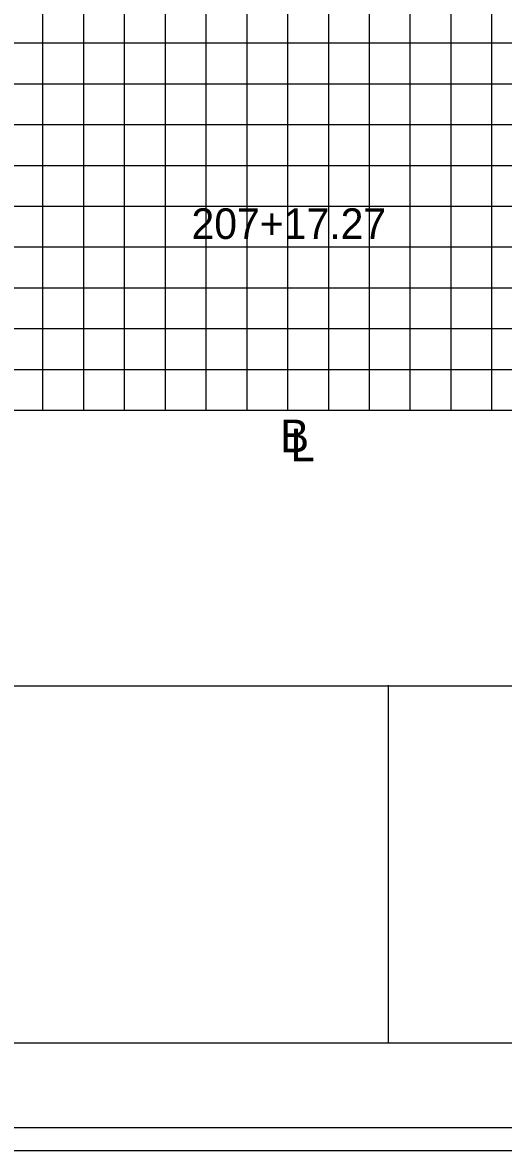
# Model space of a CAD drawing. Extents: x 967 to 1326, y 964 to 1744.
# Drawn here: x 1147 to 1170.6, y 963.7 to 1019 of the extents above; entities that cross this region are included whole.
import ezdxf

# ---------------------------------------------------------------- set-up
doc = ezdxf.new("R2010")
doc.units = 0
for name, color, linetype in [('Default', 7, 'Continuous'), ('RD_PD_PaveShd', 7, 'Continuous'), ('RD_XS_CurbBase', 7, 'Continuous'), ('RD_XS_TX_Elev_PR', 7, 'Continuous'), ('RD_XS_TX_MkPT', 7, 'Continuous'), ('RD_XS_TX_Slope', 7, 'Continuous'), ('RD_XS_TX_TOC', 7, 'Continuous')]:
    doc.layers.add(name, color=color, linetype=linetype)

msp = doc.modelspace()

# ---------------------------------------------------------------- linework, layer by layer
at = {"layer": 'RD_PD_PaveShd'}
for p, q in [((996.114, 986.486), (1323.886, 986.486)), ((1164.932, 968.983), (1164.932, 986.526)), ((1323.886, 968.983), (996.114, 968.983))]:
    msp.add_line(p, q, dxfattribs=at)
at = {"layer": 'RD_XS_CurbBase'}
msp.add_lwpolyline([(967.409, 963.72), (1326.285, 963.72), (1326.285, 1183.72), (967.409, 1183.72)], close=True, dxfattribs=at)
at = {"layer": 'RD_XS_TX_Elev_PR'}
for p, q in [((1150, 1000), (1150, 1170)), ((1160, 1000), (1160, 1170)), ((1170, 1000), (1170, 1170)), ((1000, 1010), (1320, 1010)), ((1000, 1000), (1320, 1000))]:
    msp.add_line(p, q, dxfattribs=at)
at = {"layer": 'RD_XS_TX_Slope'}
for p, q in [((1148, 1000), (1148, 1170)), ((1152, 1000), (1152, 1170)), ((1154, 1000), (1154, 1170)), ((1156, 1000), (1156, 1170)), ((1158, 1000), (1158, 1170)), ((1162, 1000), (1162, 1170)), ((1164, 1000), (1164, 1170)), ((1166, 1000), (1166, 1170)), ((1168, 1000), (1168, 1170)), ((1000, 1018), (1320, 1018)), ((1000, 1016), (1320, 1016)), ((1000, 1014), (1320, 1014)), ((1000, 1012), (1320, 1012)), ((1000, 1008), (1320, 1008)), ((1000, 1006), (1320, 1006)), ((1000, 1004), (1320, 1004)), ((1000, 1002), (1320, 1002))]:
    msp.add_line(p, q, dxfattribs=at)
at = {"layer": 'RD_XS_TX_TOC'}
for points in [[(967.409, 963.72), (1326.285, 963.72), (1326.285, 1183.72), (967.409, 1183.72)], [(988.525, 964.84), (1326.285, 964.84), (1326.285, 1182.6), (988.525, 1182.6)]]:
    msp.add_lwpolyline(points, close=True, dxfattribs=at)

# ---------------------------------------------------------------- texts
at = {"layer": 'Default'}
msp.add_text('207+17.27', height=1.5, dxfattribs=at).set_placement((1155.279, 1008.394))
at = {"layer": 'RD_XS_TX_MkPT'}
for s, p in [('B', (1159.615, 997.941)), ('L', (1160.124, 997.491))]:
    msp.add_text(s, height=1.6, dxfattribs=at).set_placement(p)

doc.saveas('drawing.dxf')
